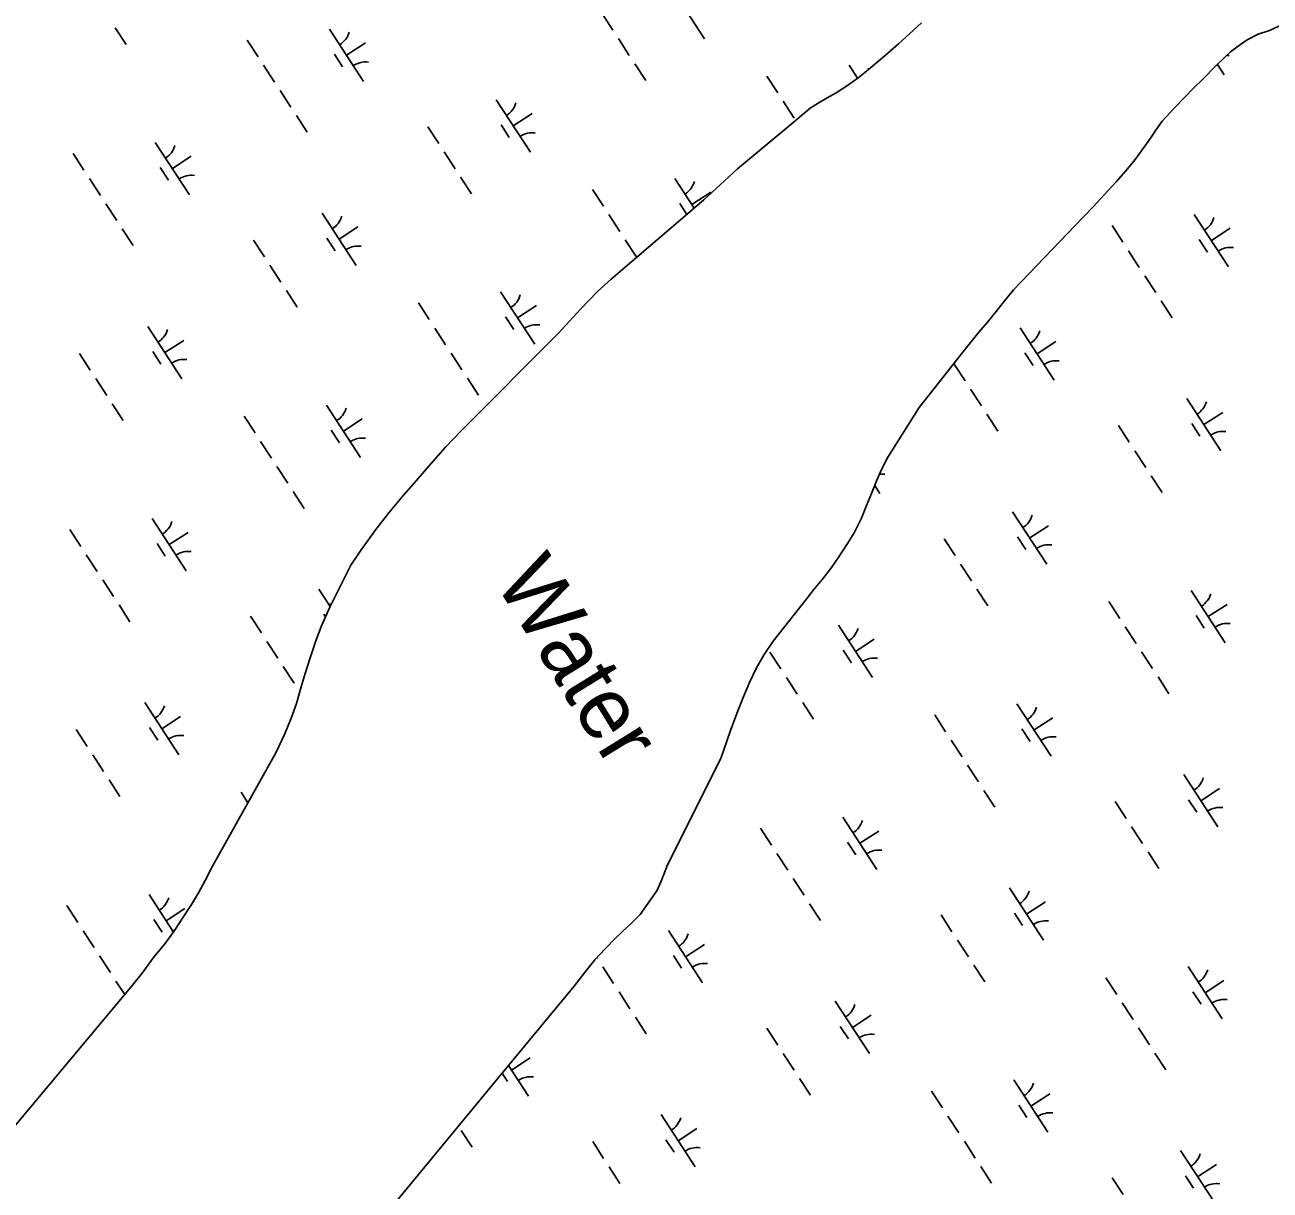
# Model space of a CAD drawing. Extents: x 3953924 to 3974542, y 193747 to 216192.
# Drawn here: x 3963008 to 3964005, y 202084 to 203017 of the extents above; entities that cross this region are included whole.
import ezdxf

# ---------------------------------------------------------------- set-up
doc = ezdxf.new("R2010")
doc.units = 0
for name, color, linetype in [('V-RIVR-IDEN', 7, 'Continuous'), ('V-TOPO-SHOR', 7, 'Continuous'), ('V-WETL-SWMP', 7, 'Continuous')]:
    doc.layers.add(name, color=color, linetype=linetype)

msp = doc.modelspace()

# ---------------------------------------------------------------- linework, layer by layer
at = {"layer": 'V-TOPO-SHOR'}
for points in [[(3962998.08, 202132.78), (3963086.41, 202238.66), (3963094.33, 202248.15), (3963102.14, 202257.77), (3963111.26, 202270.28), (3963120.22, 202281.14), (3963127.52, 202291.15), (3963134.98, 202302.55), (3963141.52, 202312.83), (3963147.03, 202322.11), (3963152.42, 202331.9), (3963158.48, 202343.33), (3963209.08, 202434.21), (3963215.97, 202448.79), (3963221.29, 202461.88), (3963225.46, 202473.73), (3963229.27, 202487.1), (3963232.39, 202497.7), (3963236.44, 202510.18), (3963241.29, 202524.68), (3963245.69, 202535.88), (3963252.33, 202550.85), (3963268.96, 202584.28), (3963276.8, 202595.93), (3963289.05, 202612.82), (3963299.34, 202626.19), (3963311.42, 202640.68), (3963321.4, 202651.9), (3963332.96, 202665.51), (3963344.89, 202678.85), (3963357.45, 202691.81), (3963435.22, 202770.23), (3963452.97, 202789.42), (3963466.44, 202803.5), (3963477.29, 202813.31), (3963551.47, 202876.83), (3963564.65, 202888.76), (3963578.6, 202901.68), (3963622.83, 202938.38), (3963636.51, 202950.17), (3963642.93, 202954.36), (3963650.11, 202958.41), (3963657.55, 202962.57), (3963666.42, 202968.37), (3963675.81, 202975.04), (3963686.64, 202983.96), (3963696.57, 202992.4), (3963707.41, 203001.7), (3963716.2, 203009.78), (3963725.63, 203018.6)], [(3963681.83, 202632.11), (3963685.68, 202641.65), (3963689.94, 202652.45), (3963692.98, 202659.22), (3963697.86, 202669.5), (3963723.83, 202710.62), (3963762.88, 202760.09), (3963771.95, 202771.18), (3963778.55, 202779.02), (3963785.42, 202787.49), (3963791.38, 202794.84), (3963799.29, 202804.68), (3963855.2, 202862.93), (3963863.34, 202871.64), (3963871.88, 202880.96), (3963881.56, 202891.27), (3963889.2, 202900.11), (3963896.59, 202909.2), (3963903.6, 202918.68), (3963908.42, 202925.54), (3963913.23, 202932.66), (3963918.18, 202939.78), (3963928.51, 202950.71), (3963943.75, 202966.48), (3963951.23, 202973.67), (3963960.78, 202983.48), (3963969.03, 202991.55), (3963973.02, 202995.27), (3963979.19, 202999.83), (3963986.37, 203004.88), (3963995.06, 203009.51), (3964004.23, 203012.5), (3964012.15, 203016.27)], [(3963305.65, 202075.26), (3963387.41, 202174.39), (3963447.9, 202247.35), (3963457.9, 202260.44), (3963464.38, 202268.29), (3963472.52, 202277.11), (3963480.65, 202285.43), (3963486.46, 202291.14), (3963493.41, 202297.46), (3963500.51, 202304.66), (3963513.91, 202323.63), (3963517.34, 202331.28), (3963522.54, 202344.59), (3963565.05, 202429.54), (3963572.95, 202452.04), (3963578.82, 202467.86), (3963582.95, 202478.54), (3963588.11, 202490.33), (3963593.78, 202502.11), (3963599.94, 202512.75), (3963606.98, 202523.62), (3963633.17, 202556.51), (3963639.66, 202564.99), (3963647.56, 202574.45), (3963653.79, 202582.55), (3963659.53, 202591.17), (3963666.44, 202601.79), (3963671.79, 202610.29), (3963677.71, 202621.95), (3963681.83, 202632.11)]]:
    msp.add_lwpolyline(points, dxfattribs=at)
at = {"layer": 'V-WETL-SWMP'}
for p, q in [((3963524.83, 203047.73), (3963552.11, 203005.82)), ((3963470.07, 203026.05), (3963478.8, 203012.64)), ((3963725.63, 203018.6), (3963716.2, 203009.78)), ((3964004.23, 203012.5), (3964012.15, 203016.27)), ((3963080.54, 203014.65), (3963089.27, 203001.24)), ((3963252, 203013.6), (3963279.28, 202971.69)), ((3963483.17, 203005.94), (3963491.9, 202992.53)), ((3963716.2, 203009.78), (3963707.41, 203001.7)), ((3963986.37, 203004.88), (3963995.06, 203009.51)), ((3963995.06, 203009.51), (3964004.23, 203012.5)), ((3963186.18, 203004.67), (3963194.91, 202991.26)), ((3963265.64, 202992.65), (3963280.73, 203002.47)), ((3963707.41, 203001.7), (3963696.58, 202992.4)), ((3963973.03, 202995.27), (3963979.19, 202999.83)), ((3963979.19, 202999.83), (3963986.37, 203004.88)), ((3963255.9, 202993.47), (3963262.45, 202983.41)), ((3963696.58, 202992.4), (3963686.64, 202983.96)), ((3963960.78, 202983.48), (3963969.03, 202991.55)), ((3963969.03, 202991.55), (3963973.03, 202995.27)), ((3963199.28, 202984.55), (3963208.01, 202971.14)), ((3963496.26, 202985.82), (3963504.99, 202972.41)), ((3963667.72, 202984.77), (3963674.61, 202974.18)), ((3963686.64, 202983.96), (3963675.81, 202975.04)), ((3963951.23, 202973.67), (3963960.78, 202983.48)), ((3963962.5, 202985.17), (3963967.82, 202976.99)), ((3963601.9, 202975.84), (3963610.63, 202962.43)), ((3963666.42, 202968.37), (3963657.55, 202962.58)), ((3963675.81, 202975.04), (3963666.42, 202968.37)), ((3963928.51, 202950.71), (3963943.75, 202966.48)), ((3963943.75, 202966.48), (3963951.23, 202973.67)), ((3963212.37, 202964.44), (3963221.1, 202951.03)), ((3963385.43, 202956.98), (3963412.7, 202915.08)), ((3963650.11, 202958.41), (3963642.93, 202954.36)), ((3963657.55, 202962.58), (3963650.11, 202958.41)), ((3963614.99, 202955.72), (3963623.72, 202942.31)), ((3963636.51, 202950.17), (3963622.83, 202938.38)), ((3963642.93, 202954.36), (3963636.51, 202950.17)), ((3963918.18, 202939.78), (3963928.51, 202950.71)), ((3963225.46, 202944.32), (3963234.19, 202930.91)), ((3963389.32, 202936.85), (3963395.87, 202926.79)), ((3963399.06, 202936.03), (3963414.15, 202945.85)), ((3963622.83, 202938.38), (3963578.6, 202901.68)), ((3963913.23, 202932.66), (3963918.18, 202939.78)), ((3963330.67, 202935.3), (3963339.4, 202921.9)), ((3963908.42, 202925.54), (3963913.23, 202932.66)), ((3963112.6, 202922.85), (3963139.88, 202880.95)), ((3963896.59, 202909.2), (3963903.6, 202918.68)), ((3963903.6, 202918.68), (3963908.42, 202925.54)), ((3963046.78, 202913.92), (3963055.51, 202900.51)), ((3963126.24, 202901.9), (3963141.32, 202911.72)), ((3963343.76, 202915.19), (3963352.49, 202901.78)), ((3963889.2, 202900.11), (3963896.59, 202909.2)), ((3963116.5, 202902.72), (3963123.05, 202892.66)), ((3963578.6, 202901.68), (3963564.65, 202888.76)), ((3963881.56, 202891.27), (3963889.2, 202900.11)), ((3963059.87, 202893.81), (3963068.6, 202880.4)), ((3963356.86, 202895.08), (3963365.58, 202881.67)), ((3963528.32, 202894.02), (3963543.79, 202870.25)), ((3963564.65, 202888.76), (3963551.47, 202876.83)), ((3963871.87, 202880.96), (3963881.56, 202891.27)), ((3963462.5, 202885.09), (3963471.22, 202871.68)), ((3963551.47, 202876.83), (3963477.29, 202813.31)), ((3963541.95, 202873.07), (3963557.04, 202882.89)), ((3963863.34, 202871.63), (3963871.87, 202880.96)), ((3963072.97, 202873.69), (3963081.69, 202860.28)), ((3963532.21, 202873.89), (3963537.88, 202865.19)), ((3963855.2, 202862.93), (3963863.34, 202871.63)), ((3963246.02, 202866.24), (3963273.3, 202824.33)), ((3963475.59, 202864.98), (3963484.32, 202851.57)), ((3963799.29, 202804.68), (3963855.2, 202862.93)), ((3963944.03, 202865.19), (3963971.31, 202823.29)), ((3963086.06, 202853.58), (3963094.79, 202840.17)), ((3963259.66, 202845.29), (3963274.74, 202855.11)), ((3963878.21, 202856.26), (3963886.94, 202842.85)), ((3963957.67, 202844.24), (3963972.75, 202854.06)), ((3963191.26, 202844.56), (3963199.99, 202831.15)), ((3963249.92, 202846.1), (3963256.47, 202836.05)), ((3963488.68, 202844.86), (3963497.41, 202831.45)), ((3963947.93, 202845.06), (3963954.48, 202835)), ((3963891.3, 202836.15), (3963900.03, 202822.74)), ((3963204.36, 202824.45), (3963213.09, 202811.04)), ((3963477.29, 202813.31), (3963466.44, 202803.5)), ((3963904.4, 202816.03), (3963913.13, 202802.62)), ((3963217.45, 202804.33), (3963226.18, 202790.92)), ((3963388.91, 202803.28), (3963416.19, 202761.37)), ((3963466.44, 202803.5), (3963452.97, 202789.42)), ((3963791.38, 202794.84), (3963799.29, 202804.68)), ((3963323.09, 202794.35), (3963331.82, 202780.94)), ((3963402.55, 202782.33), (3963417.63, 202792.15)), ((3963452.97, 202789.42), (3963435.22, 202770.23)), ((3963778.55, 202779.02), (3963785.42, 202787.49)), ((3963785.42, 202787.49), (3963791.38, 202794.84)), ((3963917.49, 202795.92), (3963926.22, 202782.51)), ((3963392.81, 202783.15), (3963399.36, 202773.09)), ((3963771.95, 202771.18), (3963778.55, 202779.02)), ((3963106.62, 202775.49), (3963133.89, 202733.59)), ((3963336.18, 202774.23), (3963344.91, 202760.82)), ((3963435.22, 202770.23), (3963357.45, 202691.8)), ((3963762.88, 202760.1), (3963771.95, 202771.18)), ((3963804.63, 202774.45), (3963831.9, 202732.54)), ((3963120.25, 202754.54), (3963135.34, 202764.36)), ((3963723.84, 202710.62), (3963762.88, 202760.1)), ((3963818.26, 202753.5), (3963833.35, 202763.32)), ((3963051.86, 202753.82), (3963060.59, 202740.41)), ((3963110.52, 202755.36), (3963117.06, 202745.3)), ((3963349.28, 202754.12), (3963358.01, 202740.71)), ((3963808.53, 202754.31), (3963815.07, 202744.26)), ((3963751.9, 202745.4), (3963760.63, 202731.99)), ((3963064.95, 202733.7), (3963073.68, 202720.29)), ((3963362.37, 202734), (3963371.1, 202720.6)), ((3963764.99, 202725.29), (3963773.72, 202711.88)), ((3963938.05, 202717.83), (3963965.32, 202675.93)), ((3963078.05, 202713.59), (3963086.78, 202700.18)), ((3963249.51, 202712.53), (3963276.78, 202670.63)), ((3963697.86, 202669.5), (3963723.84, 202710.62)), ((3963183.69, 202703.6), (3963192.42, 202690.19)), ((3963263.15, 202691.58), (3963278.23, 202701.4)), ((3963778.09, 202705.17), (3963786.81, 202691.76)), ((3963941.95, 202697.7), (3963948.49, 202687.64)), ((3963951.69, 202696.88), (3963966.77, 202706.7)), ((3963253.41, 202692.4), (3963259.95, 202682.34)), ((3963357.45, 202691.8), (3963344.89, 202678.85)), ((3963883.29, 202696.15), (3963892.02, 202682.74)), ((3963196.78, 202683.49), (3963205.51, 202670.08)), ((3963344.89, 202678.85), (3963332.96, 202665.51)), ((3963692.98, 202659.22), (3963697.86, 202669.5)), ((3963896.38, 202676.04), (3963905.11, 202662.63)), ((3963209.87, 202663.37), (3963218.6, 202649.96)), ((3963332.96, 202665.51), (3963321.4, 202651.9)), ((3963689.94, 202652.45), (3963692.98, 202659.22)), ((3963321.4, 202651.9), (3963311.42, 202640.68)), ((3963685.68, 202641.65), (3963689.94, 202652.45)), ((3963688.29, 202648.27), (3963692.5, 202641.8)), ((3963909.48, 202655.93), (3963918.21, 202642.52)), ((3963222.97, 202643.26), (3963231.69, 202629.85)), ((3963311.42, 202640.68), (3963299.33, 202626.2)), ((3963681.83, 202632.11), (3963685.68, 202641.65)), ((3963677.71, 202621.94), (3963681.83, 202632.11)), ((3963110.1, 202621.79), (3963137.38, 202579.89)), ((3963299.33, 202626.2), (3963289.05, 202612.82)), ((3963671.79, 202610.29), (3963677.71, 202621.94)), ((3963798.64, 202627.09), (3963825.92, 202585.18)), ((3963044.28, 202612.86), (3963053.01, 202599.45)), ((3963123.74, 202600.84), (3963138.83, 202610.66)), ((3963289.05, 202612.82), (3963276.8, 202595.93)), ((3963666.44, 202601.79), (3963671.79, 202610.29)), ((3963812.28, 202606.13), (3963827.37, 202615.95)), ((3963114, 202601.66), (3963120.55, 202591.6)), ((3963659.53, 202591.17), (3963666.44, 202601.79)), ((3963743.89, 202605.41), (3963752.62, 202592)), ((3963802.54, 202606.95), (3963809.09, 202596.9)), ((3963057.38, 202592.74), (3963066.1, 202579.33)), ((3963276.8, 202595.93), (3963268.96, 202584.28)), ((3963653.79, 202582.55), (3963659.53, 202591.17)), ((3963268.96, 202584.28), (3963252.33, 202550.85)), ((3963647.56, 202574.45), (3963653.79, 202582.55)), ((3963756.98, 202585.3), (3963765.71, 202571.89)), ((3963070.47, 202572.63), (3963079.2, 202559.22)), ((3963639.66, 202564.99), (3963647.56, 202574.45)), ((3963243.52, 202565.17), (3963252.55, 202551.3)), ((3963633.17, 202556.51), (3963639.66, 202564.99)), ((3963770.07, 202565.18), (3963778.8, 202551.77)), ((3963941.53, 202564.13), (3963968.81, 202522.22)), ((3963083.56, 202552.52), (3963092.29, 202539.11)), ((3963252.33, 202550.85), (3963245.69, 202535.88)), ((3963606.98, 202523.62), (3963633.17, 202556.51)), ((3963875.71, 202555.2), (3963884.44, 202541.79)), ((3963955.17, 202543.18), (3963970.26, 202553)), ((3963188.77, 202543.5), (3963197.5, 202530.09)), ((3963247.42, 202545.04), (3963248.81, 202542.91)), ((3963945.43, 202543.99), (3963951.98, 202533.94)), ((3963245.69, 202535.88), (3963241.29, 202524.68)), ((3963659.24, 202536.34), (3963686.52, 202494.44)), ((3963888.81, 202535.08), (3963897.53, 202521.67)), ((3963201.86, 202523.38), (3963210.59, 202509.97)), ((3963241.29, 202524.68), (3963236.44, 202510.18)), ((3963599.94, 202512.75), (3963606.98, 202523.62)), ((3963672.88, 202515.39), (3963687.96, 202525.21)), ((3963236.44, 202510.18), (3963232.39, 202497.7)), ((3963593.78, 202502.11), (3963599.94, 202512.75)), ((3963604.48, 202514.66), (3963613.21, 202501.26)), ((3963663.14, 202516.21), (3963669.68, 202506.15)), ((3963901.9, 202514.97), (3963910.63, 202501.56)), ((3963214.95, 202503.27), (3963223.68, 202489.86)), ((3963588.11, 202490.33), (3963593.78, 202502.11)), ((3963232.39, 202497.7), (3963229.27, 202487.1)), ((3963582.95, 202478.54), (3963588.11, 202490.33)), ((3963617.58, 202494.55), (3963626.3, 202481.14)), ((3963914.99, 202494.85), (3963923.72, 202481.44)), ((3963229.27, 202487.1), (3963225.46, 202473.73)), ((3963578.82, 202467.86), (3963582.95, 202478.54)), ((3963104.12, 202474.43), (3963131.4, 202432.52)), ((3963225.46, 202473.73), (3963221.29, 202461.88)), ((3963572.95, 202452.04), (3963578.82, 202467.86)), ((3963630.67, 202474.44), (3963639.4, 202461.03)), ((3963802.13, 202473.38), (3963829.41, 202431.48)), ((3963117.76, 202453.48), (3963132.84, 202463.3)), ((3963221.29, 202461.88), (3963215.96, 202448.79)), ((3963736.31, 202464.45), (3963745.04, 202451.04)), ((3963815.77, 202452.43), (3963830.85, 202462.25)), ((3963049.36, 202452.75), (3963058.09, 202439.34)), ((3963108.02, 202454.3), (3963114.56, 202444.24)), ((3963215.96, 202448.79), (3963209.08, 202434.21)), ((3963565.05, 202429.54), (3963572.95, 202452.04)), ((3963806.03, 202453.25), (3963812.57, 202443.19)), ((3963749.4, 202444.34), (3963758.13, 202430.93)), ((3963062.46, 202432.64), (3963071.18, 202419.23)), ((3963209.08, 202434.21), (3963158.48, 202343.33)), ((3963522.54, 202344.59), (3963565.05, 202429.54)), ((3963762.49, 202424.22), (3963771.22, 202410.81)), ((3963075.55, 202412.52), (3963084.28, 202399.11)), ((3963935.55, 202416.77), (3963962.83, 202374.86)), ((3963181.19, 202402.54), (3963186.72, 202394.04)), ((3963775.59, 202404.11), (3963784.32, 202390.7)), ((3963949.19, 202395.82), (3963964.27, 202405.63)), ((3963880.79, 202395.09), (3963889.52, 202381.68)), ((3963939.45, 202396.63), (3963946, 202386.58)), ((3963662.72, 202382.64), (3963690, 202340.73)), ((3963596.9, 202373.71), (3963605.63, 202360.3)), ((3963676.36, 202361.69), (3963691.45, 202371.51)), ((3963893.89, 202374.98), (3963902.62, 202361.57)), ((3963666.62, 202362.51), (3963673.17, 202352.45)), ((3963610, 202353.59), (3963618.73, 202340.18)), ((3963906.98, 202354.86), (3963915.71, 202341.45)), ((3963158.48, 202343.33), (3963152.42, 202331.9)), ((3963517.34, 202331.28), (3963522.54, 202344.59)), ((3963152.42, 202331.9), (3963147.03, 202322.11)), ((3963513.91, 202323.63), (3963517.34, 202331.28)), ((3963623.09, 202333.48), (3963631.82, 202320.07)), ((3963107.6, 202320.72), (3963127.17, 202290.67)), ((3963147.03, 202322.11), (3963141.52, 202312.83)), ((3963500.51, 202304.66), (3963513.91, 202323.63)), ((3963796.15, 202326.02), (3963823.42, 202284.12)), ((3963041.78, 202311.79), (3963050.51, 202298.38)), ((3963121.24, 202299.77), (3963136.33, 202309.59)), ((3963141.52, 202312.83), (3963134.98, 202302.55)), ((3963636.18, 202313.36), (3963644.91, 202299.96)), ((3963809.78, 202305.07), (3963824.87, 202314.89)), ((3963111.5, 202300.59), (3963118.05, 202290.53)), ((3963134.98, 202302.55), (3963127.52, 202291.15)), ((3963493.41, 202297.46), (3963500.51, 202304.66)), ((3963741.39, 202304.34), (3963750.12, 202290.94)), ((3963800.04, 202305.89), (3963806.59, 202295.83)), ((3963054.88, 202291.68), (3963063.61, 202278.27)), ((3963127.52, 202291.15), (3963120.22, 202281.14)), ((3963480.65, 202285.43), (3963486.46, 202291.14)), ((3963486.46, 202291.14), (3963493.41, 202297.46)), ((3963523.32, 202291.89), (3963550.6, 202249.99)), ((3963120.22, 202281.14), (3963111.26, 202270.28)), ((3963472.52, 202277.11), (3963480.65, 202285.43)), ((3963536.96, 202270.94), (3963552.04, 202280.76)), ((3963754.48, 202284.23), (3963763.21, 202270.82)), ((3963067.97, 202271.56), (3963076.7, 202258.16)), ((3963111.26, 202270.28), (3963102.14, 202257.77)), ((3963464.38, 202268.29), (3963472.52, 202277.11)), ((3963465.95, 202269.99), (3963466.23, 202269.55)), ((3963527.22, 202271.76), (3963533.77, 202261.7)), ((3963447.9, 202247.35), (3963457.9, 202260.44)), ((3963457.9, 202260.44), (3963464.38, 202268.29)), ((3963470.59, 202262.85), (3963479.32, 202249.44)), ((3963767.58, 202264.12), (3963776.3, 202250.71)), ((3963939.04, 202263.06), (3963966.31, 202221.16)), ((3963081.06, 202251.45), (3963088.09, 202240.66)), ((3963102.14, 202257.77), (3963094.34, 202248.15)), ((3963873.22, 202254.13), (3963881.94, 202240.72)), ((3963952.67, 202242.11), (3963967.76, 202251.93)), ((3963086.41, 202238.66), (3962998.08, 202132.78)), ((3963094.34, 202248.15), (3963086.41, 202238.66)), ((3963387.41, 202174.39), (3963447.9, 202247.35)), ((3963483.69, 202242.73), (3963492.41, 202229.32)), ((3963942.93, 202242.93), (3963949.48, 202232.87)), ((3963656.74, 202235.28), (3963684.02, 202193.37)), ((3963886.31, 202234.02), (3963895.04, 202220.61)), ((3963496.78, 202222.62), (3963505.51, 202209.21)), ((3963670.38, 202214.33), (3963685.46, 202224.15)), ((3963601.99, 202213.6), (3963610.71, 202200.19)), ((3963660.64, 202215.15), (3963667.19, 202205.09)), ((3963899.4, 202213.9), (3963908.13, 202200.49)), ((3963397.55, 202180.2), (3963412.64, 202190.02)), ((3963615.08, 202193.49), (3963623.81, 202180.08)), ((3963912.49, 202193.79), (3963921.22, 202180.38)), ((3963395.21, 202183.8), (3963411.19, 202159.25)), ((3963305.65, 202075.26), (3963387.41, 202174.39)), ((3963390.05, 202177.58), (3963394.36, 202170.96)), ((3963628.17, 202173.37), (3963636.9, 202159.96)), ((3963799.63, 202172.32), (3963826.91, 202130.41)), ((3963733.81, 202163.39), (3963742.54, 202149.98)), ((3963813.27, 202151.37), (3963828.36, 202161.19)), ((3963803.53, 202152.19), (3963810.08, 202142.13)), ((3963517.34, 202144.53), (3963544.61, 202102.63)), ((3963746.9, 202143.27), (3963755.63, 202129.86)), ((3963357.37, 202131.88), (3963366.1, 202118.47)), ((3963530.98, 202123.58), (3963546.06, 202133.4)), ((3963462.58, 202122.86), (3963471.31, 202109.45)), ((3963521.24, 202124.4), (3963527.78, 202114.34)), ((3963760, 202123.16), (3963768.73, 202109.75)), ((3963933.05, 202115.7), (3963960.33, 202073.8)), ((3963475.67, 202102.74), (3963484.4, 202089.33)), ((3963773.09, 202103.04), (3963781.82, 202089.64)), ((3963946.69, 202094.75), (3963961.78, 202104.57)), ((3963878.3, 202094.02), (3963887.02, 202080.62)), ((3963936.95, 202095.57), (3963943.5, 202085.51))]:
    msp.add_line(p, q, dxfattribs=at)
for centre, start, end in [((3963250.77, 203015.92), 302.29009, 343.83375), ((3963280.91, 202969.63), 82.29009, 123.83375), ((3963969.45, 202974.92), 82.29009, 87.91237), ((3963666.49, 202987.09), 339.6686, 343.83375), ((3963384.19, 202959.31), 302.29009, 343.83375), ((3963414.33, 202913.01), 82.29009, 123.83375), ((3963111.37, 202925.18), 302.29009, 343.83375), ((3963141.51, 202878.88), 82.29009, 123.83375), ((3963527.08, 202896.35), 302.29009, 343.83375), ((3963244.79, 202868.56), 302.29009, 343.83375), ((3963942.8, 202867.52), 302.29009, 343.83375), ((3963274.93, 202822.27), 82.29009, 123.83375), ((3963972.94, 202821.22), 82.29009, 123.83375), ((3963387.68, 202805.6), 302.29009, 343.83375), ((3963417.82, 202759.31), 82.29009, 123.83375), ((3963105.39, 202777.82), 302.29009, 343.83375), ((3963803.4, 202776.77), 302.29009, 343.83375), ((3963135.52, 202731.52), 82.29009, 123.83375), ((3963833.53, 202730.48), 82.29009, 123.83375), ((3963248.28, 202714.86), 302.29009, 343.83375), ((3963936.82, 202720.16), 302.29009, 343.83375), ((3963966.95, 202673.86), 82.29009, 123.83375), ((3963278.41, 202668.56), 82.29009, 123.83375), ((3963694.13, 202639.73), 82.29009, 96.6451), ((3963108.87, 202624.12), 302.29009, 343.83375), ((3963797.41, 202629.41), 302.29009, 343.83375), ((3963827.55, 202583.12), 82.29009, 123.83375), ((3963139.01, 202577.82), 82.29009, 123.83375), ((3963940.3, 202566.45), 302.29009, 343.83375), ((3963242.29, 202567.5), 302.29009, 312.0724), ((3963970.44, 202520.16), 82.29009, 123.83375), ((3963658.01, 202538.67), 302.29009, 343.83375), ((3963688.14, 202492.37), 82.29009, 123.83375), ((3963102.89, 202476.76), 302.29009, 343.83375), ((3963800.9, 202475.71), 302.29009, 343.83375), ((3963133.02, 202430.46), 82.29009, 123.83375), ((3963831.03, 202429.41), 82.29009, 123.83375), ((3963934.32, 202419.09), 302.29009, 343.83375), ((3963964.46, 202372.8), 82.29009, 123.83375), ((3963661.49, 202384.97), 302.29009, 343.83375), ((3963691.63, 202338.67), 82.29009, 123.83375), ((3963794.91, 202328.35), 302.29009, 343.83375), ((3963106.37, 202323.05), 302.29009, 343.83375), ((3963825.05, 202282.05), 82.29009, 123.83375), ((3963136.51, 202276.75), 117.7413, 123.83375), ((3963522.09, 202294.22), 302.29009, 343.83375), ((3963552.23, 202247.92), 82.29009, 123.83375), ((3963937.8, 202265.39), 302.29009, 343.83375), ((3963655.51, 202237.6), 302.29009, 343.83375), ((3963967.94, 202219.09), 82.29009, 123.83375), ((3963685.65, 202191.31), 82.29009, 123.83375), ((3963412.82, 202157.18), 82.29009, 123.83375), ((3963798.4, 202174.65), 302.29009, 343.83375), ((3963516.11, 202146.86), 302.29009, 343.83375), ((3963828.54, 202128.35), 82.29009, 123.83375), ((3963546.24, 202100.56), 82.29009, 123.83375), ((3963931.82, 202118.03), 302.29009, 343.83375), ((3963961.96, 202071.73), 82.29009, 123.83375)]:
    msp.add_arc(centre, 17.62, start, end, dxfattribs=at)

# ---------------------------------------------------------------- texts
at = {"layer": 'V-RIVR-IDEN'}
msp.add_text('Water', height=50, rotation=301.66125, dxfattribs=at).set_placement((3963383.38, 202571.64))

doc.saveas('drawing.dxf')
